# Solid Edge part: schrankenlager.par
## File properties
Author: Wir
Template: Normal.par
Last saved by: Wir
Revision: 2
Application: Solid Edge
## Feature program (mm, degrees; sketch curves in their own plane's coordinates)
sketch for "unnamed Protrusion 1" plane through (0, 0, 0) normal (0, 0, 1) x-axis (1, 0, 0)
extrude "unnamed Protrusion 1" add finite 60 along +normal
sketch for "unnamed Cutout 1" plane through (0, 0, 0) normal (1, 0, 0) x-axis (0, 1, 0)
extrude "unnamed Cutout 1" cut finite 152.4 symmetric
sketch for "unnamed Protrusion 2" plane through (0, 0, 0) normal (0, -1, 0) x-axis (1, 0, 0)
  line (-2.5, 55) -> (-2.5, 60)
  line (-2.5, 60) -> (-7.5, 65)
  line (-7.5, 65) -> (-7.5, 50)
  line (-7.5, 50) -> (7.5, 50)
  line (7.5, 50) -> (7.5, 65)
  line (2.5, 60) -> (7.5, 65)
  line (2.5, 60) -> (2.5, 55)
  line (2.5, 55) -> (-2.5, 55)
extrude "unnamed Protrusion 2" add finite 10 symmetric
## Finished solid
Body 1: solid body, 14 faces, 36 edges, 24 vertices.
  Faces by surface: plane 14
  Edges by curve: line 36
Bounding box of the edges (mm): 15.000 x 10.000 x 65.000, from (-7.5, -5, 0) to (7.5, 5, 65).
Planar faces by outward normal: +x 3, +y 1, +z 1, -x 3, -y 1, -z 3, oblique 2
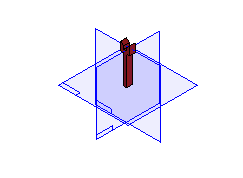
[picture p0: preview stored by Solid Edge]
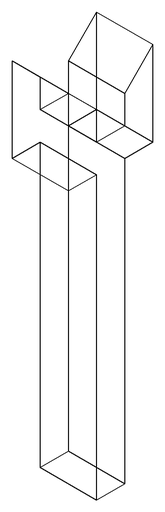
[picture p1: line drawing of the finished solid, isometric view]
